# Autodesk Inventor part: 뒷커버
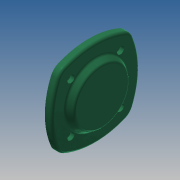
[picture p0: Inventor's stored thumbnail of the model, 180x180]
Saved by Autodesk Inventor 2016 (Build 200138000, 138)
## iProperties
Created: 2015-11
Part Number: 뒷커버
Material: 알루미늄 6061
Document SubType Name: Modeling
Designer: mduedu
Density: 2.71 g/cm^3
Appearance: 매끄러움 - 짙은 바다 녹색
Mass: 325.35 g
Surface Area: 247.582 cm^2
Volume: 120.055 cm^3
Author: mduedu
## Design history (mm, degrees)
sketch "스케치1"
  geometry: L1 (50, 50)-(-50, 50); L2 (-50, 50)-(-50, -50); L3 (-50, -50)-(50, -50); L4 (50, -50)-(50, 50); L5 (0, 50)-(0, -50); L6 (50, 0)-(-50, 0); A1 r 90 centre (-40, 0) between (40.415, -40.415) and (40.415, 40.415); A2 r 90 centre (40, 0) between (-40.415, 40.415) and (-40.415, -40.415); A3 r 90 centre (0, -40) between (40.415, 40.415) and (-40.415, 40.415); A4 r 90 centre (0, 40) between (-40.415, -40.415) and (40.415, -40.415); 2 further points
  constraints: 12 end point, 8 point on circle, 5 midpoint, 4 centre point, 2 horizontal alignment, 2 parallel, 2 perpendicular, 2 symmetric about line, 2 tangent, 2 vertical alignment, 1 equal radius, 1 horizontal, 2 other
  dimensions: "d0" = 100 distance of L3.end L1.start; "d2" = 90 radius of A1
extrude "돌출1" new body sketch "스케치1" distance "d3" = 8; taper "d4" = 0 deg
sketch "스케치2"
  geometry: C1 r 35 at (0, 0); 1 further point
  constraints: 1 centre point, 1 coincident
  dimensions: "d5" = 70 diameter of C1
extrude "돌출2" join sketch "스케치2" distance "d6" = 7; taper "d7" = -30 deg
sketch "스케치3"
  geometry: L1 (0, 0)-(0, 40); L2 (0, 0)-(-28.284, 28.284); A1 r 40 centre (0, 0) between (0, 40) and (-28.284, 28.284); 2 further points
  constraints: 4 end point, 2 coincident, 2 point on circle, 1 centre point, 1 vertical
  dimensions: "d8" = 80 diameter of A1; "d9" = 45 deg angle of L1 L2
hole "구멍1" sketch "스케치3" at (-28.284, 28.284) diameter "d11" = 4.5; stored, may be unused: countersink angle "d15" = 90 deg, drill point angle "d17" = 118 deg; dims "d12" = 6, "d13" = 8, "d14" = 4.4, "d16" = 8
sketch "스케치4"
  geometry: C1 r 35 at (0, 0); 1 further point
  constraints: 1 centre point, 1 coincident
  dimensions: "d21" = 70 diameter of C1
extrude "돌출3" join sketch "스케치4" distance "d23" = 12; taper "d24" = 0 deg
hole "구멍2" diameter "d27" = 30; stored, may be unused: countersink angle "d31" = 90 deg, drill point angle "d33" = 0 deg; dims "d25" = 10, "d26" = 10, "d28" = 6, "d29" = 40, "d30" = 12, "d32" = 15
fillet "모깎기2" dims "d35" = 15
fillet "모깎기3" dims "d36" = 3
fillet "모깎기4" dims "d37" = 3
fillet "모깎기5" dims "d38" = 0.3
chamfer "모따기1" distance "d39" = 1; stored, may be unused: second distance "d40" = 2, angle "d41" = 45 deg
node "솔리드1"
pattern_circular "원형 패턴1" dims angle "d19" = 360 deg
